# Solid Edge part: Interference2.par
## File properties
Last saved by: user
Revision: 51
Accuracy: 0.99
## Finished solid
Body 1: solid body, 4 faces, 4 edges, 2 vertices.
  Faces by surface: cone 2, plane 2
  Edges by curve: circle 2, intersection 1, line 1
Bounding box of the edges (mm): 0.037 x 0.085 x 0.148, from (0.5503, -0.0852, 10.9259) to (0.587, 0, 11.0741).
Conical faces (half-angle, radius in mm at the cone's reference point): 27.3968 deg R0.0554 x2
Planar faces by outward normal: +x 1, oblique 1
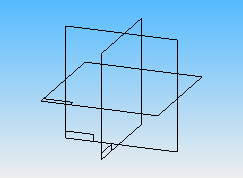
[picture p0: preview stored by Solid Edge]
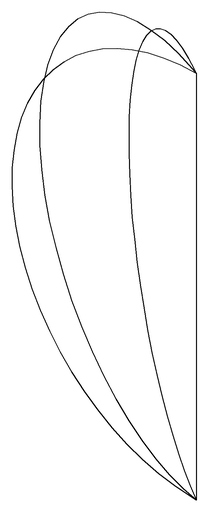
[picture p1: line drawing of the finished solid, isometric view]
